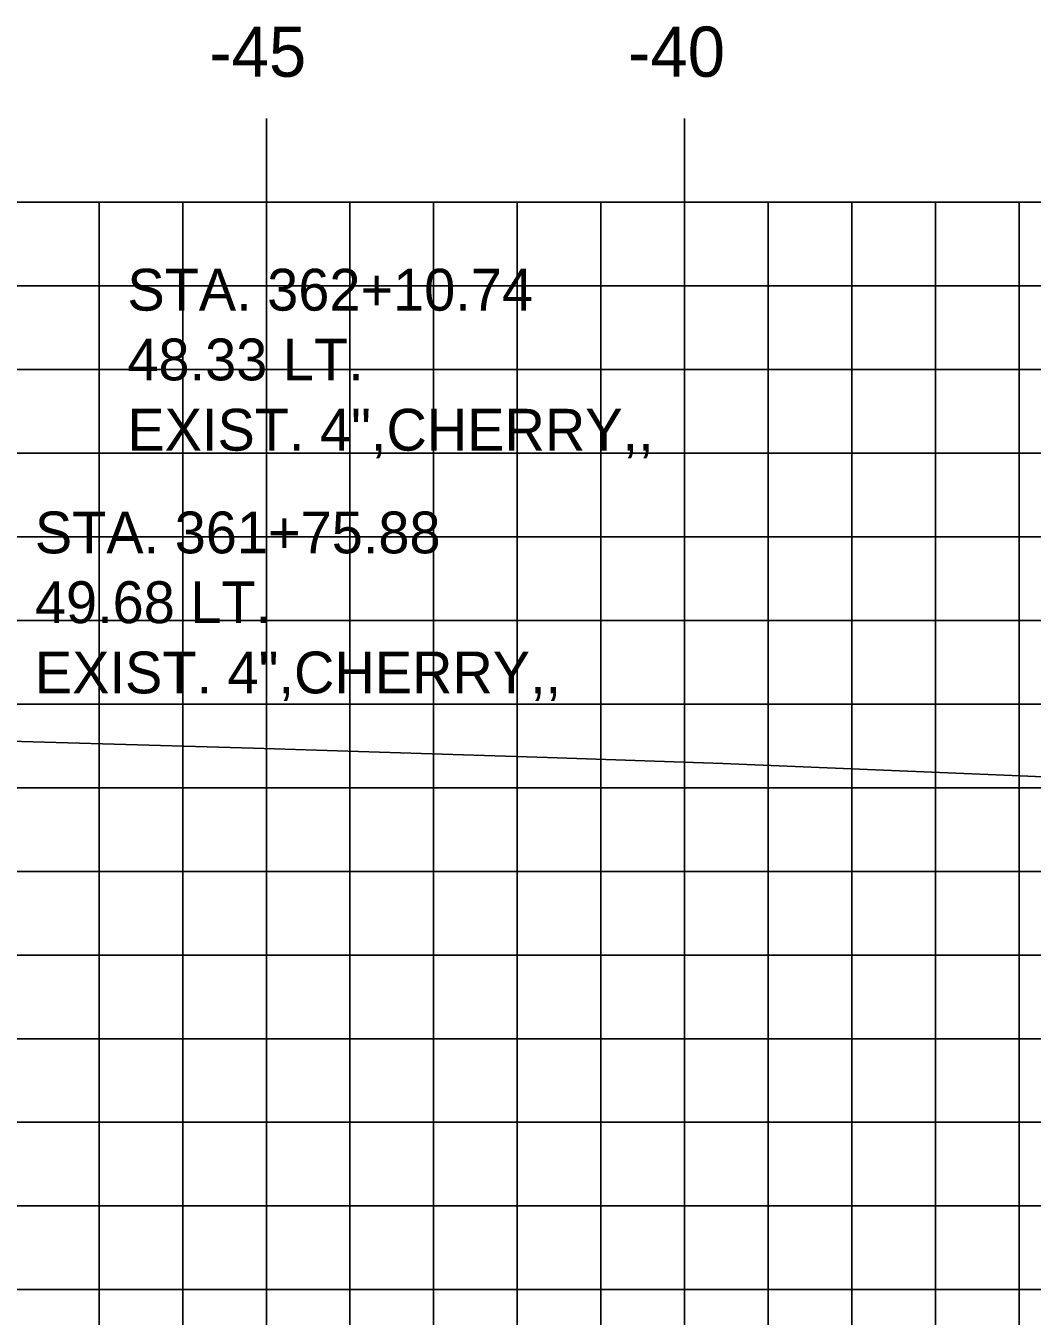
# Model space of a CAD drawing. Extents: x 1146746 to 1146916, y 608981 to 609091.
# Drawn here: x 1146781.55 to 1146793.59, y 608997.02 to 609012.44 of the extents above; entities that cross this region are included whole.
import ezdxf

# ---------------------------------------------------------------- set-up
doc = ezdxf.new("R2010")
doc.units = 0
for name, color, linetype in [('D_Text_Monospaced', 7, 'Continuous'), ('H_V ANNOTATION', 7, 'Continuous'), ('MAJOR', 7, 'Continuous'), ('MINOR', 7, 'Continuous'), ('S_Roadway_Centerline', 7, 'Continuous')]:
    doc.layers.add(name, color=color, linetype=linetype)

msp = doc.modelspace()

# ---------------------------------------------------------------- linework, layer by layer
at = {"layer": 'MAJOR'}
for p, q in [((1146784.428, 609011.337), (1146784.428, 609010.335)), ((1146789.428, 609011.337), (1146789.428, 609010.335)), ((1146759.428, 609010.335), (1146899.428, 609010.335)), ((1146759.428, 609010.335), (1146899.428, 609010.335)), ((1146784.428, 608990.335), (1146784.428, 609010.335)), ((1146789.428, 608990.335), (1146789.428, 609010.335)), ((1146759.428, 609005.335), (1146899.428, 609005.335)), ((1146759.428, 609000.335), (1146899.428, 609000.335))]:
    msp.add_line(p, q, dxfattribs=at)
at = {"layer": 'MINOR'}
for p, q in [((1146782.428, 608990.335), (1146782.428, 609010.335)), ((1146783.428, 608990.335), (1146783.428, 609010.335)), ((1146785.428, 608990.335), (1146785.428, 609010.335)), ((1146786.428, 608990.335), (1146786.428, 609010.335)), ((1146787.428, 608990.335), (1146787.428, 609010.335)), ((1146788.428, 608990.335), (1146788.428, 609010.335)), ((1146790.428, 608990.335), (1146790.428, 609010.335)), ((1146791.428, 608990.335), (1146791.428, 609010.335)), ((1146792.428, 608990.335), (1146792.428, 609010.335)), ((1146793.428, 608990.335), (1146793.428, 609010.335)), ((1146759.428, 609009.335), (1146899.428, 609009.335)), ((1146759.428, 609008.335), (1146899.428, 609008.335)), ((1146759.428, 609007.335), (1146899.428, 609007.335)), ((1146759.428, 609006.335), (1146899.428, 609006.335)), ((1146759.428, 609004.335), (1146899.428, 609004.335)), ((1146759.428, 609003.335), (1146899.428, 609003.335)), ((1146759.428, 609002.335), (1146899.428, 609002.335)), ((1146759.428, 609001.335), (1146899.428, 609001.335)), ((1146759.428, 608999.335), (1146899.428, 608999.335)), ((1146759.428, 608998.335), (1146899.428, 608998.335)), ((1146759.428, 608997.335), (1146899.428, 608997.335))]:
    msp.add_line(p, q, dxfattribs=at)
at = {"layer": 'S_Roadway_Centerline'}
msp.add_lwpolyline([(1146759.428, 609004.302), (1146759.453, 609004.302), (1146761.53, 609004.279), (1146765.65, 609004.222), (1146768.621, 609004.171), (1146770.506, 609004.133), (1146774.204, 609004.064), (1146778.345, 609003.971), (1146780.383, 609003.919), (1146784.273, 609003.81), (1146787.791, 609003.697), (1146789.886, 609003.623), (1146793.44, 609003.479), (1146796.798, 609003.331)], dxfattribs=at)

# ---------------------------------------------------------------- texts
at = {"layer": 'D_Text_Monospaced'}
for s, height, p in [('STA. 362+10.74', 0.49998, (1146782.766, 609009.039)), ('48.33 LT.', 0.5, (1146782.766, 609008.205)), ('EXIST. 4",CHERRY,,', 0.49998, (1146782.766, 609007.365)), ('STA. 361+75.88', 0.49998, (1146781.66, 609006.137)), ('49.68 LT.', 0.5, (1146781.66, 609005.303)), ('EXIST. 4",CHERRY,,', 0.49998, (1146781.66, 609004.463))]:
    msp.add_text(s, height=height, dxfattribs=at).set_placement(p)
at = {"layer": 'H_V ANNOTATION'}
for s, p in [('-45', (1146783.745, 609011.835)), ('-40', (1146788.753, 609011.835))]:
    msp.add_text(s, height=0.6, dxfattribs=at).set_placement(p)

doc.saveas('drawing.dxf')
